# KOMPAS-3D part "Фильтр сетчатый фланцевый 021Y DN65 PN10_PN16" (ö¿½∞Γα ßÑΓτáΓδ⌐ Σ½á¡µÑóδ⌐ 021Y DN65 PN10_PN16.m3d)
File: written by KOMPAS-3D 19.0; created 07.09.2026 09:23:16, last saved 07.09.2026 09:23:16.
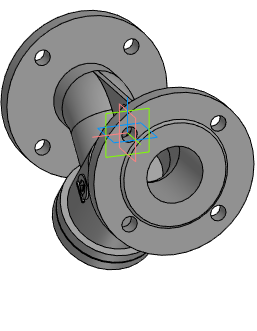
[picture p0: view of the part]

Document properties: Автор: Энергия; Полное имя файла: Z:\3.Личные\sachek\Dendor\_3D для проектировщиков\8.3 Фильтр сетчатый 021Y\021Y_STP\Фильтр сетчатый фланцевый 021Y DN65 PN10_PN16.m3d

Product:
- Part/product: Фильтр сетчатый фланцевый 021Y DN65 PN10_PN16

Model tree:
1. Операция без истории:1  (labels: Фильтр сетчатый фланцевый 021Y DN65 PN10_PN16)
